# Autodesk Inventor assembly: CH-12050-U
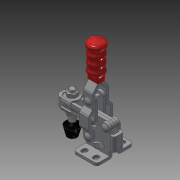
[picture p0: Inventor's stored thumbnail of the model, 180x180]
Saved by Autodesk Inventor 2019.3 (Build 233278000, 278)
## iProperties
Company: Î¢ÈíÖÐ¹ú
Created: 2015-08
Part Number: CH-12050-U
Material: Ogólny
Description: STEP AP203
Document SubType Name: Assembly
Designer: CADENGINEERING4
Stock Number: DOCISK PIONOWY
Sending System: SolidWorks 2012
Preprocessor: SwSTEP 2.0
Title: CH-12050-U.STEP
Author: Î¢ÈíÓÃ»§
Revision Number: ÈÎºÎ
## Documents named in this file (11)
- D:\Vault_2016\Projekty\Clamptek\STRONA\Vertical toggle clamp\CH-12050-U\CH-12050-U_ZAMKNIETY.iam
- D:\Vault_2016\Projekty\Clamptek\STRONA\Vertical toggle clamp\CH-12050-U\CH-12050-01 FLANGED BASE.ipt
- D:\Vault_2016\Projekty\Clamptek\STRONA\Vertical toggle clamp\CH-12050-U\CH-12050-04 CONNECTING-PLATE.ipt
- D:\Vault_2016\Projekty\Clamptek\STRONA\Vertical toggle clamp\CH-12050-U\CH-12050-03 STRAIGHT HANDLE.ipt
- D:\Vault_2016\Projekty\Clamptek\STRONA\Vertical toggle clamp\CH-12050-U\CH-12050-07.ipt
- D:\Vault_2016\Projekty\Clamptek\STRONA\Vertical toggle clamp\CH-12050-U\CH-12050-06.ipt
- D:\Vault_2016\Projekty\Clamptek\STRONA\Vertical toggle clamp\CH-12050-U\CH-FW-140.ipt
- D:\Vault_2016\Projekty\Clamptek\STRONA\Vertical toggle clamp\CH-12050-U\CH-12050-05.ipt
- D:\Vault_2016\Projekty\Clamptek\STRONA\Vertical toggle clamp\CH-12050-U\CH-12050-U-02 U-BAR.ipt
- D:\Vault_2016\Projekty\Clamptek\STRONA\Vertical toggle clamp\CH-12050-U\CH-FC-14134 Nut.ipt
- D:\Vault_2016\Projekty\Clamptek\STRONA\Vertical toggle clamp\CH-12050-U\CH-FC-14134 SPINDLE SUPPLIED.ipt
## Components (14 placed, 14 different names)
1. CH-12050-01 FLANGED BASE_1
2. CH-12050-04 CONNECTING-PLATE_2
3. CH-12050-03 STRAIGHT HANDLE_3
4. CH-12050-07_4
5. CH-12050-07_5
6. CH-12050-06_6
7. CH-12050-06_7
8. CH-FW-140_8
9. CH-FW-140_9
10. CH-12050-05_10
11. CH-12050-U-02 U-BAR_11
12. CH-FC-14134 Nut_12
13. CH-FC-14134 SPINDLE SUPPLIED_13
14. CH-FC-14134 Nut_14
